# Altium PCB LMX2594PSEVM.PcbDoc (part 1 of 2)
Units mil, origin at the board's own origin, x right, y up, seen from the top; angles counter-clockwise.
Board outline 1260 x 3135 mil, 4 copper layers (Top Layer, GND, Power, Bottom Layer), stack 61.6 mil thick; 123 components, 80 nets, 426 pads, 190 vias.
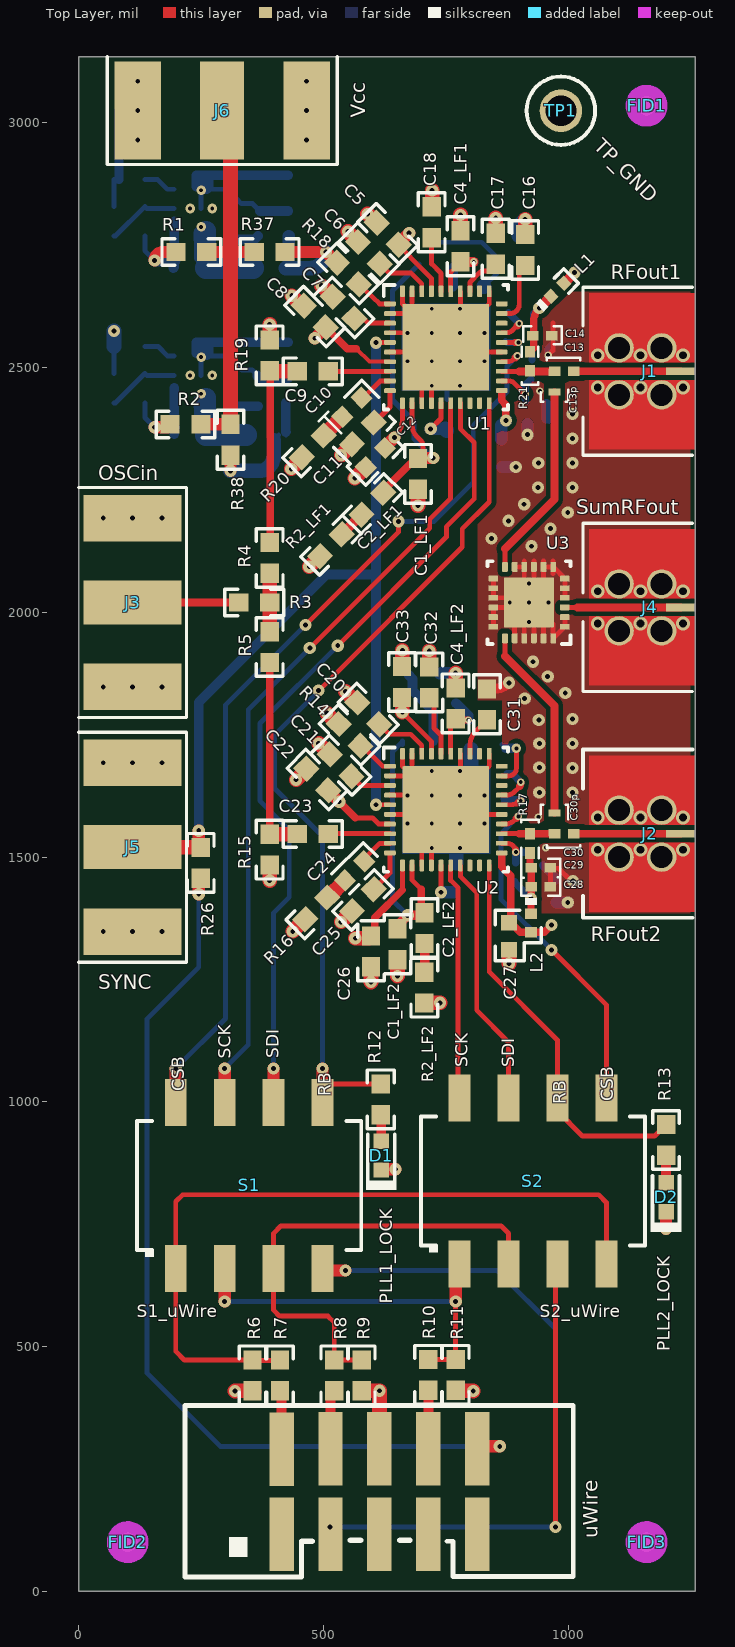
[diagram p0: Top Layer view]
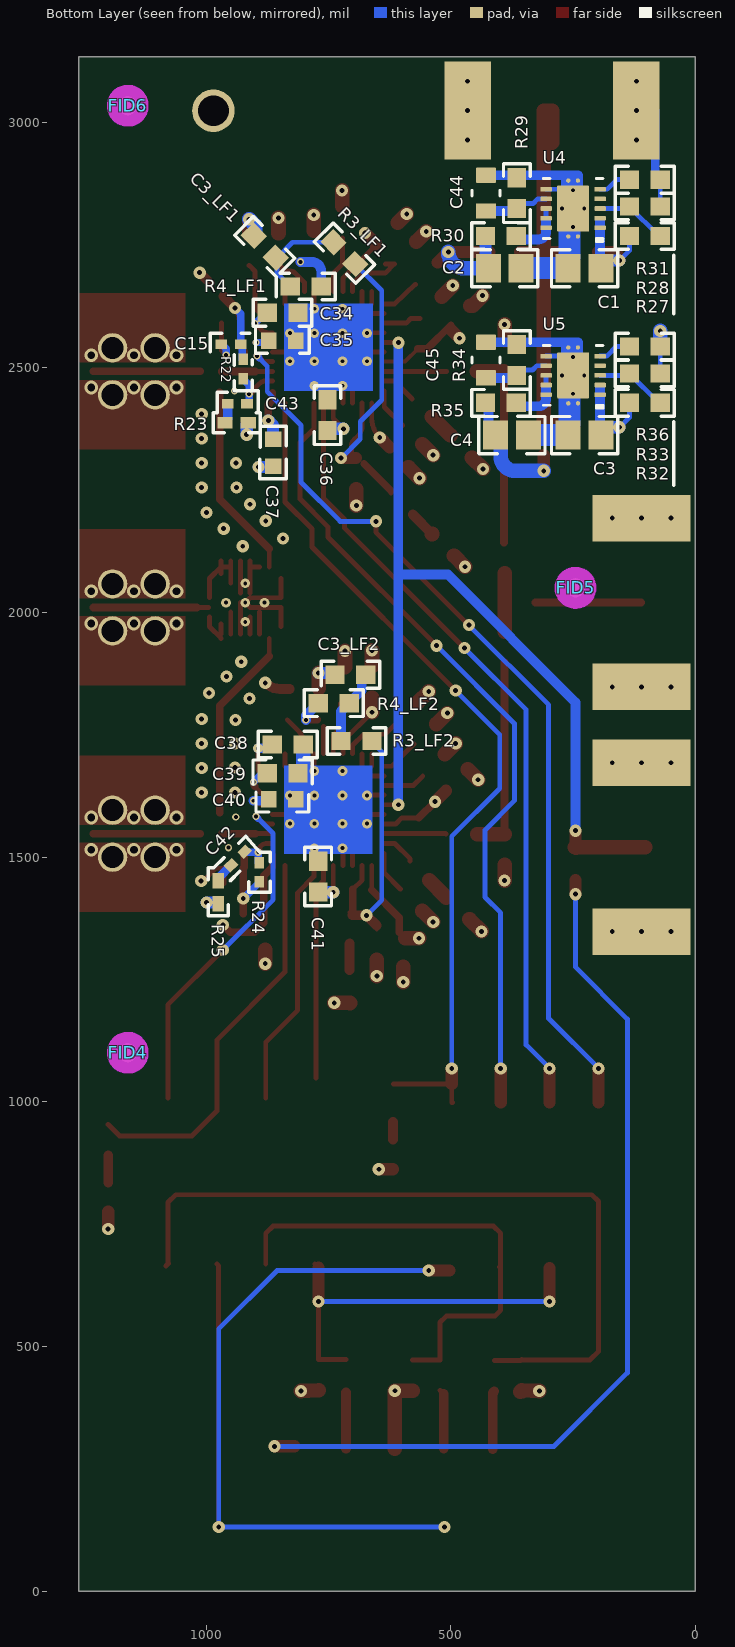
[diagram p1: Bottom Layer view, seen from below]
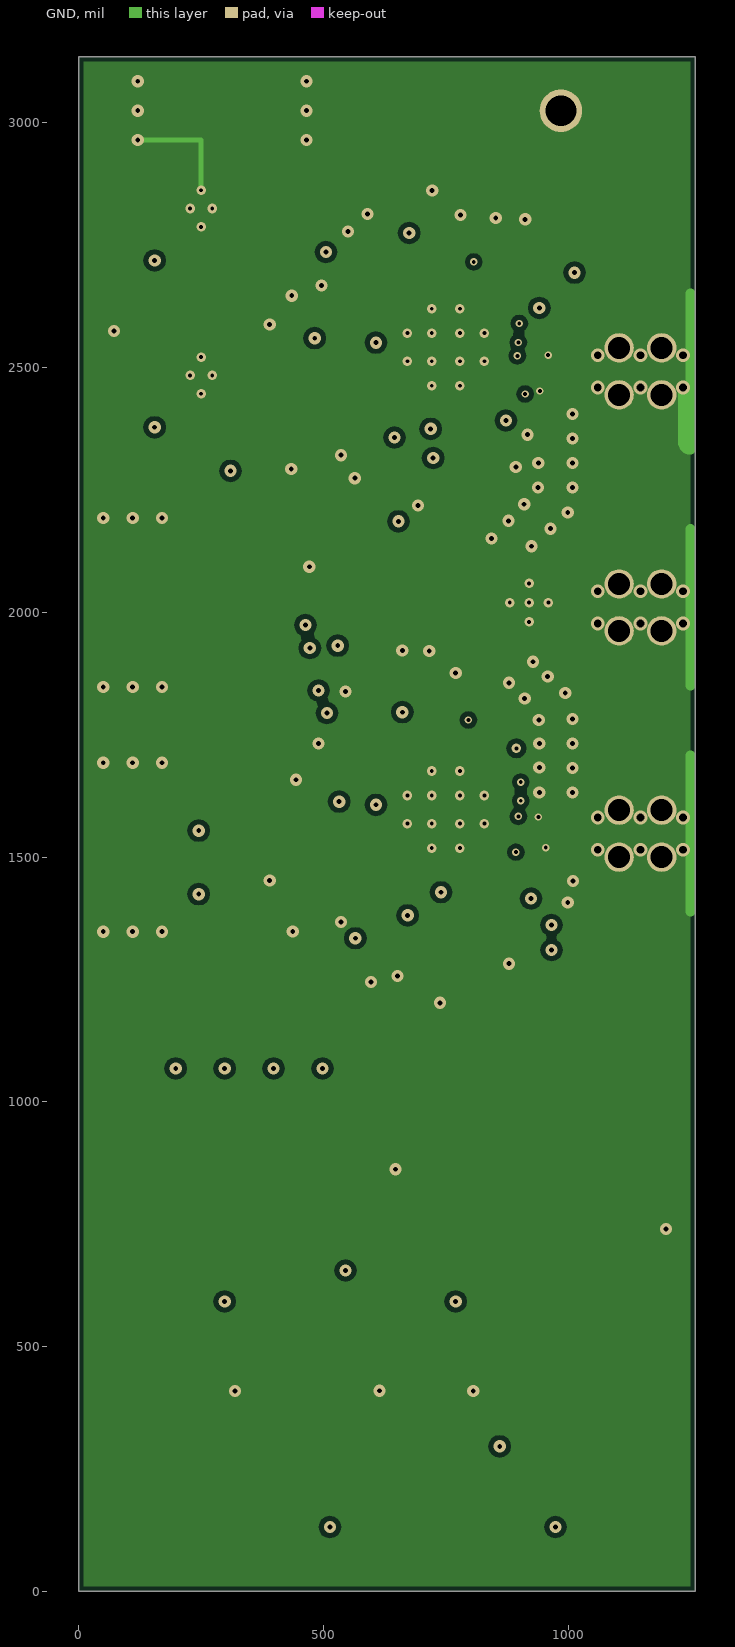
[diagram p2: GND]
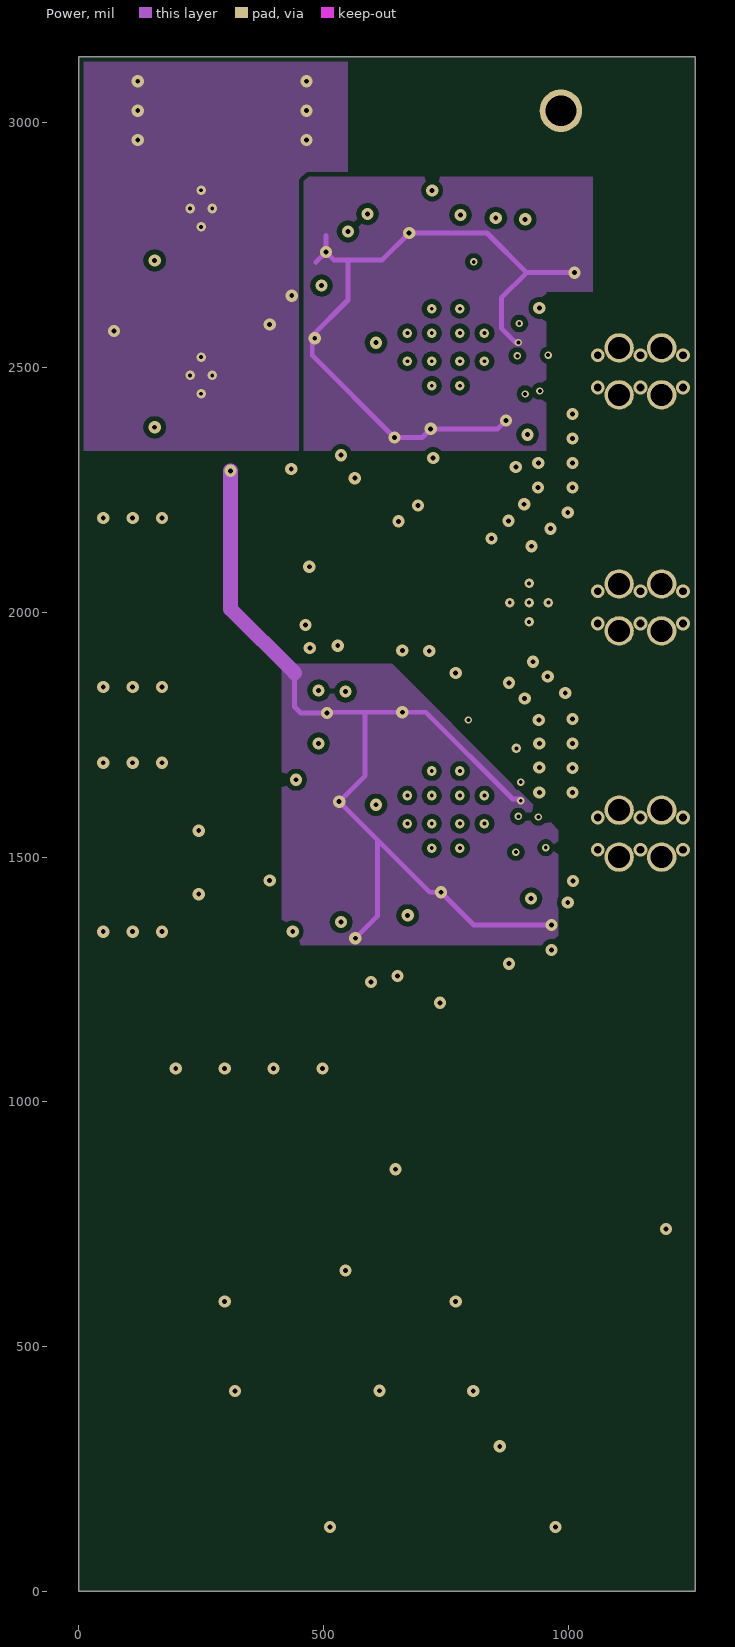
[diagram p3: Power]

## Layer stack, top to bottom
Top Solder: solder mask 0.4, Solder Resist, Dk 3.5
Top Layer: signal copper 1.4
Dielectric 1: prepreg 8, RO4350B, Dk 3.66
GND: signal copper 1.4
Dielectric 2: core 40, FR-4 High Tg, Dk 4.2
Power: signal copper 1.4
Dielectric 3: prepreg 8, FR-4 High Tg, Dk 4.2
Bottom Layer: signal copper 1.4
Bottom Solder: solder mask 0.4, Solder Resist, Dk 3.5

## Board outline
0,-0.14 0,3134.86 1260,3134.86 1260,-0.14

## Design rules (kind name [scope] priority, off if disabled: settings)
AcuteAngle [All] p1: minimum=4.50000000000000E+0001 checktracksonly=FALSE
AssemblyTestPointUsage [All] p1: valid=2
BoardOutlineClearance BoardOutlineClearance_MountingHoles [OnCopper and InComponentClass('Mounting Holes')] p1: gap=39.37 ignorepadtopadclearanceinfootprint=FALSE
BoardOutlineClearance BoardOutlineClearance_Poly [OnCopper and IsPoly] p2: gap=25 ignorepadtopadclearanceinfootprint=FALSE except(10: Poly-OutlineEdge)
BoardOutlineClearance [OnCopper and not InComponentClass('Logo')and not InComponentClass('FiducialMark') and not InRegion (1000, 500, 4000, 800) and not InPoly and not InComponent('J1') and not InComponent('J2') and not InComponent('J3') and not InComponent('J4') and not InComponent('J5') and not InComponent('J6') and not IsVia and not InNet('NetC13_2') and not InNet('NetC30_1') and not InNet('NetJ4_1') and not InNet('GND')] p3: gap=40 ignorepadtopadclearanceinfootprint=FALSE
Clearance Clearance_Keepouts [((IsTrack or IsArc) and not InPoly) and IsFree and IsKeepOut vs ((IsTrack or IsArc) and not InPoly) and IsFree and IsKeepOut] p1: gap=0 ignorepadtopadclearanceinfootprint=FALSE
Clearance Clearance_Poly [InPolygon] p2: gap=10 ignorepadtopadclearanceinfootprint=TRUE
Clearance Clearance_FiducialMark [IsKeepOut and InComponentClass('FiducialMark') vs IsPad and InComponentClass('FiducialMark')] p3: gap=0 ignorepadtopadclearanceinfootprint=FALSE
Clearance [All] p4: gap=7.87 ignorepadtopadclearanceinfootprint=TRUE
ComponentClearance ComponentClearance_MountingHoles_FiducialMarks [InComponentClass('Mounting Holes') vs InComponentClass('FiducialMark')] p1: gap=50 collisioncheckmode=3 verticalgap=10 showdistances=FALSE
ComponentClearance ComponentClearance_Shunt [InComponentClass('Header') vs InComponentClass('Shunt')] p2: gap=0 collisioncheckmode=3 verticalgap=0 showdistances=FALSE
ComponentClearance ComponentClearance_Logo [InComponentClass('Logo')] p3: gap=30 collisioncheckmode=3 verticalgap=10 showdistances=FALSE
ComponentClearance ComponentClearance_ScrewToNut [(HasFootprint('NY PMS 440 0025 PH')) vs (HasFootprint('Keystone_1902C'))] p4: gap=5 collisioncheckmode=3 verticalgap=10 showdistances=FALSE
ComponentClearance ComponentClearance_MountingHoles [InComponentClass('Mounting Holes')] p5: gap=100 collisioncheckmode=3 verticalgap=100000 showdistances=FALSE
ComponentClearance ComponentClearance_SmallPassives [not InComponent('C13') and not InComponent('C13p') and not InComponent('C30') and not InComponent('C30p') vs HasFootprint('0201*') or HasFootprint('0402*') or HasFootprint('0508') or HasFootprint('0603*') or HasFootprint('0612') or HasFootprint('0805*') or HasFootprint('0815*') or HasFootprint('0830*') or HasFootprint('1206*') or HasFootprint('1210*') or HasFootprint('1808*') or HasFootprint('1812*') or HasFootprint('1825*') or HasFootprint('2010*') or HasFootprint('2220*') or HasFootprint('2225*') or HasFootprint('2512*') or HasFootprint('2728*') or HasFootprint('3518*') or HasFootprint('IND_LQG*')] p6: gap=14.96 collisioncheckmode=3 verticalgap=10 showdistances=FALSE
ComponentClearance ComponentClearance_THtoSMT [IsThruComponent vs IsSMTComponent] p7: gap=30 collisioncheckmode=3 verticalgap=30 showdistances=FALSE
ComponentClearance ComponentClearance_THtoTH [IsThruComponent vs IsThruComponent] p8: gap=20 collisioncheckmode=3 verticalgap=30 showdistances=FALSE
ComponentClearance [not InComponent('C13') and not InComponent('C13p') and not InComponent('C30') and not InComponent('C30p')] p9: gap=20 collisioncheckmode=3 verticalgap=10 showdistances=FALSE
DiffPairsRouting [All] p1 off: maxlimit=100 minlimit=10 mostfreqgap=10 toplayer_minwidth=15 toplayer_maxwidth=15 toplayer_prefwidth=15 midlayer1_minwidth=15 midlayer1_maxwidth=15 midlayer1_prefwidth=15 midlayer2_minwidth=15 midlayer2_maxwidth=15 midlayer2_prefwidth=15 bottomlayer_minwidth=15 bottomlayer_maxwidth=15 bottomlayer_prefwidth=15 maxuncoupledlength=1000
FabricationTestPointUsage TestPointUsage [All] p1: valid=2 allowmultiple=FALSE
FabricationTestpoint Testpoint [All] p1: side=3 testpointundercomponent=TRUE minsize=40 maxsize=100 preferedsize=60 minholesize=0 maxholesize=40 preferedholesize=32 testpointgrid=1 allowsidetop=TRUE allowsidebottom=TRUE usegrid=TRUE gridtolerance=0.01
FanoutControl Fanout_LCC [IsLCC] p1 off: bgadir=Out bgaviamode=Centered fanoutstyle=Auto fanoutdirection=Alternating viagrid=1 // Fanout_LCC (Default Rule)
FanoutControl Fanout_BGA [IsBGA] p2: bgadir=Out bgaviamode=Centered fanoutstyle=Auto fanoutdirection=Alternating viagrid=1 // Fanout_BGA (Default Rule)
FanoutControl Fanout_Default [All] p4: bgadir=Out bgaviamode=Centered fanoutstyle=Auto fanoutdirection=Alternating viagrid=1 // Fanout_Default (Default Rule)
FanoutControl Fanout_Small [(CompPinCount < 5)] p5: bgadir=Out bgaviamode=Centered fanoutstyle=Auto fanoutdirection=OutThenIn viagrid=1 // Fanout_Small (Default Rule)
Height [All] p1 off: minheight=0 maxheight=1000 prefheight=500
HoleSize [All] p1 off: absolutevalues=TRUE maxlimit=251 minlimit=7.87 maxpercent=80.000 minpercent=20.000
MinimumAnnularRing MinimumAnnularRing_ThermalPadVias [IsVia and InAnyComponent] p1: minimumring=3.94
MinimumAnnularRing [All] p2: minimumring=3.5
MinimumSolderMaskSliver MinimumSolderMaskSliver_Logo [InComponentClass('Logo') vs InComponentClass('Logo')] p1: minsoldermaskwidth=3
MinimumSolderMaskSliver [All and not (InComponent('RFout1') or InComponent('RFout2')or InComponent('SumRFout')) and not InComponent('U3')] p2: minsoldermaskwidth=3.94
NetAntennae [All] p1: netantennaetolerance=1
PlaneConnect [All] p1: planeconnectstyle=Direct reliefexpansion=10 reliefentries=4 reliefconductorwidth=10 reliefairgap=10
PolygonConnect [All] p1: connectstyle=Direct reliefconductorwidth=15 reliefentries=4 polygonreliefangle="90 Angle" airgapwidth=10
RoutingVias [All] p1: holewidth=10 width=25 viastyle="Through Hole" minholewidth=2 minwidth=5 maxholewidth=16 maxwidth=30
RoutingVias ThermalPadVias [IsVia and InAnyComponent] p2: holewidth=7.87 width=19.68 viastyle="Through Hole" minholewidth=2 minwidth=5 maxholewidth=12.99 maxwidth=23.62
SMDToCorner [All] p1: distance=30000
SilkToSilkClearance SilkToSilkClearance_Pb-FreeLogo [(HasFootprint('Pb-Free_Overlay_Medium') or HasFootprint('Pb-Free_Overlay_Small')) vs (HasFootprint('Pb-Free_Overlay_Medium') or HasFootprint('Pb-Free_Overlay_Small'))] p1: silktosilkclearance=0
SilkToSilkClearance [All] p2: silktosilkclearance=3.94
SilkToSolderMaskClearance SilkscreenOverComponentPads [IsPad] p1: minsilkscreentomaskgap=3 clearancetoexposedcopper=TRUE
SolderMaskExpansion [All] p1: expansion=1.97
UnRoutedNet [All] p1: checkbadconnections=TRUE
Width [All] p1: maxlimit=200 minlimit=5 preferedwidth=5 checkconnectedcopper=TRUE
13 further rules are at their usual default settings.

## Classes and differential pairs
component class LMX2594PSEVM_SYNTH2: C1_LF2 C2_LF2 C3_LF2 C4_LF2 C20 C21 C22 C23 C24 C25 C26 C27 C28 C29 C30 C30p C31 C32 C33 C38 C39 C40 C41 C42 J2 L2 R2_LF2 R3_LF2 R4_LF2 R14 R15 R16 R17 R24 R25 U2
component class LMX2594PSEVM_HW: C1 C2 C3 C4 C44 C45 D1 D2 FID1 FID2 FID3 FID4 FID5 FID6 J3 J4 J5 J6 R1 R2 R3 R4 R5 R6 R7 R8 R9 R10 R11 R12 R13 R26 R27 R28 R29 R30 R31 R32 R33 R34 R35 R36 R37 R38 S1 S2 TP1 U3 U4 U5 uWire
component class FiducialMark: FID1 FID2 FID3 FID4 FID5 FID6
component class LMX2594PSEVM_SYNTH1: C1_LF1 C2_LF1 C3_LF1 C4_LF1 C5 C6 C7 C8 C9 C10 C11 C12 C13 C13p C14 C15 C16 C17 C18 C34 C35 C36 C37 C43 J1 L1 R2_LF1 R3_LF1 R4_LF1 R18 R19 R20 R21 R22 R23 U1

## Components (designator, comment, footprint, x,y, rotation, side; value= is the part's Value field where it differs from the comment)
C1 "EMK212BB7106KG-T" 0805 226.54,2703 r180 bottom value=10uF
C1_LF1 "06035A391JAT2A" 0603 693,2282.86 r270 top value=390pF
C1_LF2 "06035A391JAT2A" 0603 651.28,1321.69 r270 top value=390pF
C2 "EMK212BB7106KG-T" 0805 389.54,2703 r0 bottom value=10uF
C2_LF1 "885012206070" 0603 599.95,2221.81 r225 top value=0.068uF
C2_LF2 "885012206070" 0603 706.21,1354.86 r270 top value=0.068uF
C3 "EMK212BB7106KG-T" 0805 226.54,2362 r180 bottom value=10uF
C3_LF1 "GRM1885C1H301JA01D" 0603 880,2747 r45 bottom value=300pF
C3_LF2 "GRM1885C1H301JA01D" 0603 705.04,1872.36 r0 bottom value=300pF
C4 "EMK212BB7106KG-T" 0805 375,2362 r0 bottom value=10uF
C4_LF1 "Capacitor" 0603 780,2748 r90 top value=1800pF
C4_LF2 "Capacitor" 0603 770,1813.86 r90 top value=1800pF
C5 "Capacitor" 0603 631.12,2773.57 r135 top value=0.1uF
C6 "885012206052" 0603 592.83,2734.2 r135 top value=1uF
C7 "GRM188R61A106KAALD" 0603 540.81,2622.67 r135 top value=10uF
C8 "Capacitor" 0603 482.19,2604.36 r315 top value=0.1uF
C9 "Capacitor" 0603 478,2492.35 r0 top value=0.1uF
C10 "Capacitor" 0603L 558,2419 r45 top value=0.1uF
C11 "885012206052" 0603 580.51,2365.57 r45 top value=1uF
C12 "Capacitor" 0603L 606,2316 r45 top value=0.1uF
C13 "Capacitor" 0402_065L 992,2492.36 r0 top value=0.1uF
C13p "C0402C103J5RACTU" 0402S 972,2470 r270 top value=0.01uF
C14 "Capacitor" 0402_065L 947,2565 r180 top value=0.1uF
C15 "Capacitor" 0402_065L 949,2548 r180 bottom value=0.1uF
C16 "GRM188R61A106KAALD" 0603 912.05,2740.25 r90 top value=10uF
C17 "GRM188R61A106KAALD" 0603 852,2742.86 r90 top value=10uF
C18 "GRM188R61A106KAALD" 0603 721,2796.86 r90 top value=10uF
C20 "885012206052" 0603 591.49,1793.44 r135 top value=1uF
C21 "GRM188R61A106KAALD" 0603 535,1687.44 r315 top value=10uF
C22 "Capacitor" 0603 487.24,1658.37 r315 top value=0.1uF
C23 "Capacitor" 0603 478,1547 r0 top value=0.1uF
C24 "Capacitor" 0603L 563.61,1471.74 r45 top value=0.1uF
C25 "885012206052" 0603 580.41,1412.07 r45 top value=1uF
C26 "Capacitor" 0603 597,1307 r90 top value=0.1uF
C27 "Capacitor" 0603L 879,1338.25 r270 top value=0.1uF
C28 "Capacitor" 0402_065L 944,1439 r180 top value=0.1uF
C29 "Capacitor" 0402_065L 944,1478 r180 top value=0.1uF
C30 "Capacitor" 0402_065L 992,1547.65 r180 top value=0.1uF
C30p "C0402C103J5RACTU" 0402S 972,1570 r270 top value=0.01uF
C31 "GRM188R61A106KAALD" 0603 834,1812 r270 top value=10uF
C32 "GRM188R61A106KAALD" 0603 716,1856.86 r270 top value=10uF
C33 "Capacitor" 0603 660.19,1857.57 r90 top value=0.1uF
C34 "885012206052" 0603 843.71,2612 r0 bottom value=1uF
C35 "Capacitor" 0603L 844,2555 r180 bottom value=0.1uF
C36 "Capacitor" 0603 752,2402.86 r270 bottom value=0.1uF
C37 "Capacitor" 0603L 863,2326 r270 bottom value=0.1uF
C38 "GRM188R61A106KAALD" 0603 833,1730 r180 bottom value=10uF
C39 "885012206052" 0603 843.71,1671 r0 bottom value=1uF
C40 "Capacitor" 0603L 844,1617.72 r180 bottom value=0.1uF
C41 "Capacitor" 0603 771,1460 r270 bottom value=0.1uF
C42 "Capacitor" 0402_065L 935,1497 r135 bottom value=0.1uF
C43 "Capacitor" 0402_065L 936,2426 r180 bottom value=0.1uF
C44 "CGA4J1X7R1H475K125AC" FP-CGA4J1X7R1H475K125AC_0805-MFG 428,2856.42 r270 bottom value=4.7µF
C45 "CGA4J1X7R1H475K125AC" FP-CGA4J1X7R1H475K125AC_0805-MFG 428,2515.42 r270 bottom value=4.7µF
D1 "PLL1_LOCK" LED_LTST-C190 618,890 r270 top value=Green
D2 "PLL2_LOCK" LED_LTST-C190 1200,804.86 r270 top value=Green
FID1 "Fiducial" Fiducial10-20 1160,3035 r0 top
FID2 "Fiducial" Fiducial10-20 100,100 r0 top
FID3 "Fiducial" Fiducial10-20 1160,100 r0 top
FID4 "Fiducial" Fiducial10-20 1160,1100 r180 bottom
FID5 "Fiducial" Fiducial10-20 245,2050 r180 bottom
FID6 "Fiducial" Fiducial10-20 1160,3035 r180 bottom
J1 "RFout1" Johnson_142-0761-881 1147.5,2492.36 r270 top
J2 "RFout2" Johnson_142-0761-881 1147.5,1547.65 r270 top
J3 "OSCin" Emerson_142-0701-851 0,2020 r90 top
J4 "SumRFout" Johnson_142-0761-881 1147.5,2009.92 r270 top
J5 "SYNC" Emerson_142-0701-851 0,1520 r90 top
J6 "Vcc" Emerson_142-0701-851 293,3135 r0 top
L1 "Inductor_Iron" IND_LQG15H 978,2659 r45 top value=18nH
L2 "Inductor_Iron" IND_LQG15H 924,1365 r270 top value=18nH
R1 "Resistor" 0603 230,2736 r180 top value=0
R2 "Resistor" 0603 218,2384 r180 top value=0
R2_LF1 "Resistor" 0603 515,2137 r225 top value=68
R2_LF2 "Resistor" 0603 706,1233 r270 top value=68
R3 "Resistor" 0603 358.5,2020 r0 top value=18
R3_LF1 "Resistor" 0603 717.31,2733.8 r45 bottom value=18
R3_LF2 "Resistor" 0603 692.59,1736.95 r0 bottom value=18
R4 "Resistor" 0603 390,2111 r90 top value=18
R4_LF1 "Resistor" 0603 796.21,2665.82 r180 bottom value=0
R4_LF2 "Resistor" 0603 739.17,1814.27 r0 bottom value=0
R5 "Resistor" 0603 390,1929 r90 top value=18
R6 "Resistor" 0603 355,440.86 r90 top value=12k
R7 "CRCW060318R0JNEA" 0603 411,440.86 r90 top value=18
R8 "CRCW060318R0JNEA" 0603 522,440.86 r270 top value=18
R9 "Resistor" 0603 578,440.86 r90 top value=12k
R10 "CRCW060318R0JNEA" 0603 714,441.86 r90 top value=18
R11 "Resistor" 0603 770,441.86 r90 top value=12k
R12 "Resistor" 0603 617,1004.86 r90 top value=330
R13 "Resistor" 0603 1200,921.86 r90 top value=330
R14 "Resistor" 0603 553.29,1749.39 r315 top value=12k
R15 "Resistor" 0603 390,1515 r90 top value=51
R16 "Resistor" 0603 485,1395 r45 top value=51
R17 "Resistor" 0402L 922,1527.86 r90 top value=50
R18 "Resistor" 0603 549.81,2692.29 r315 top value=12k
R19 "Resistor" 0603 390,2525 r270 top value=51
R20 "Resistor" 0603 478,2339 r45 top value=51
R21 "Resistor" 0402L 922,2512.86 r270 top value=50
R22 "Resistor" 0402L 924,2497 r90 bottom value=50
R23 "Resistor" 0402 937.61,2387 r180 bottom value=50
R24 "Resistor" 0402L 891,1468.92 r270 bottom value=50
R25 "Resistor" 0402 975,1428 r270 bottom value=50
R26 "Resistor" 0603 249,1488 r270 top value=0
R27 "Resistor" 0603 103.5,2769 r0 bottom value=12k
R28 "Resistor" 0603 103.5,2829 r0 bottom value=12k
R29 "CRCW060322K1FKEA" 0603 365,2856.5 r270 bottom value=22.1k
R30 "Resistor" 0603 397.5,2769 r0 bottom value=0
R31 "Resistor" 0603 103.5,2884 r0 bottom value=12k
R32 "Resistor" 0603 103.5,2428 r0 bottom value=12k
R33 "Resistor" 0603 103.5,2488 r0 bottom value=12k
R34 "CRCW060322K1FKEA" 0603 365,2515.5 r270 bottom value=22.1k
R35 "Resistor" 0603 397.5,2428 r0 bottom value=0
R36 "Resistor" 0603 103.5,2543 r0 bottom value=12k
R37 "Resistor" 0603 390,2736 r0 top value=0
R38 "Resistor" 0603 310,2352.5 r270 top value=0
S1 "S1_uWire" SW_219-4MST 348,828.86 r90 top
S2 "S2_uWire" SW_219-4MST 928,837.86 r90 top
TP1 "TP_GND" Keystone5007 985,3024.86 r90 top
U1 "LMX2594RHAR" RHA0040H 750,2541.57 r0 top
U2 "LMX2594RHAR" RHA0040H 750,1596.86 r0 top
U3 "EP2C+" DG1847 920,2019.77 r180 top
U4 "TPS7A9401DSC" DSC0010J-MFG 250,2825 r0 bottom
U5 "TPS7A9401DSC" DSC0010J-MFG 250,2484 r0 bottom
uWire "Header_5x2" FCI_52601-S10-8LF 614.27,203.51 r90 top

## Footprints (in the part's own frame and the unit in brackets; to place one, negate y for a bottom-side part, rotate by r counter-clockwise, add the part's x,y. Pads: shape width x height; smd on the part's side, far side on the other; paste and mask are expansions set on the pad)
0402 [mm] "0402 from SM-752 data"
  rect 0.8x0.6 smd: 1(-0.6,0) 2(0.6,0)
  silkscreen extent -1.22,-1.27 1.23,1.6, body extent -0.55,-0.3 0.55,0.3, height 0.6
0402_065L [mm] "0402"
  rect 0.6x0.5 smd: 1(-0.5,0) 2(0.5,0)
  body extent -0.55,-0.3 0.55,0.3, height 0.65
0402L [mm] "0402 from SM-752 data"
  rect 0.6x0.5 smd: 1(-0.5,0) 2(0.5,0)
  body extent -0.55,-0.3 0.55,0.3, height 0.6
0402S [mil] "Based on C0402S footprint from PADS legacy"
  rect 15x24 smd: 1(-20,0) 2(20,0)
  body extent -22,-12 22,12, height 24
0603 [mm] "0603 from SM-752 data"
  rect 1x0.95 smd: 1(-0.8,0) 2(0.8,0)
  silkscreen extent -1.52,-0.69 1.52,0.69, body extent -0.87,-0.47 0.87,0.47, height 1
0603L [mm] "0603 from SM-752 data"
  rect 0.8x0.85 smd: 1(-0.7,0) 2(0.7,0)
  body extent -0.87,-0.47 0.87,0.47, height 1
0805 [mm] "0805 from SM-752 data"
  rect 1.3x1.5 smd: 1(-0.85,0) 2(0.85,0)
  silkscreen extent -1.72,-0.97 1.72,0.97, body extent -1.1,-0.72 1.1,0.72, height 1.45
DG1847 [mm] "QFN, 24-Leads, Body 4x4mm, Pitch 0.5mm"
  rrect33% 0.51x0.3 smd: 1(-1.855,1.25) 2(-1.855,0.75) 3(-1.855,0.25) 4(-1.855,-0.25) 5(-1.855,-0.75) 6(-1.855,-1.25) 13(1.855,-1.25) 14(1.855,-0.75) 15(1.855,-0.25) 16(1.855,0.25) 17(1.855,0.75) 18(1.855,1.25)
  rrect33% 0.3x0.51 smd: 7(-1.25,-1.855) 8(-0.75,-1.855) 9(-0.25,-1.855) 10(0.25,-1.855) 11(0.75,-1.855) 12(1.25,-1.855) 19(1.25,1.855) 20(0.75,1.855) 21(0.25,1.855) 22(-0.25,1.855) 23(-0.75,1.855) 24(-1.25,1.855)
  rrect4% 2.59x2.59 smd paste-2: 25(0,0)
  rrect9% 1.106x1.106 on Top Paste: ""(-0.653,0.653) ""(-0.653,-0.653) ""(0.653,0.653) ""(0.653,-0.653)
  silkscreen extent -2.15,-2.15 2.15,2.15, body extent -2,-2 2,2, height 1
DSC0010J-MFG [mm]
  rrect42% 0.6x0.24 smd paste+0 mask+0: 1(-1.4,1) 2(-1.4,0.5) 3(-1.4,0) 4(-1.4,-0.5) 5(-1.4,-1) 6(1.4,-1) 7(1.4,-0.5) 8(1.4,0) 9(1.4,0.5) 10(1.4,1)
  round 0.225 smd paste-1000 mask+0: 11(-0.25,-1.45) 11(-0.25,1.448) 11(0.25,-1.448) 11(0.25,1.45)
  rrect6% 1.65x2.4 smd paste-1000 mask+0: 11(0,0)
  Top Layer region: -0.375,1.2 -0.375,1.65 -0.371,1.669 -0.36,1.685 -0.344,1.696 -0.325,1.7 -0.325,1.7 -0.175,1.7 -0.156,1.696 -0.14,1.685 -0.129,1.669 -0.125,1.65 -0.125,1.65 -0.125,1.2
  Top Layer region: 0.125,1.2 0.125,1.65 0.129,1.669 0.14,1.685 0.156,1.696 0.175,1.7 0.175,1.7 0.325,1.7 0.344,1.696 0.36,1.685 0.371,1.669 0.375,1.65 0.375,1.65 0.375,1.2
  Top Layer region: -0.125,-1.2 -0.125,-1.65 -0.132,-1.675 -0.15,-1.693 -0.175,-1.7 -0.175,-1.7 -0.325,-1.7 -0.344,-1.696 -0.36,-1.685 -0.371,-1.669 -0.375,-1.65 -0.375,-1.65 -0.375,-1.2
  Top Layer region: 0.375,-1.2 0.375,-1.65 0.368,-1.675 0.35,-1.693 0.325,-1.7 0.325,-1.7 0.175,-1.7 0.156,-1.696 0.14,-1.685 0.129,-1.669 0.125,-1.65 0.125,-1.65 0.125,-1.2
  silkscreen extent -1.55,-1.55 1.55,1.55, body extent -1.5,-1.5 1.5,1.5, height 0.8
Emerson_142-0701-851 [mil] "Cinch Connectivity"
  rect 90x200 smd: 1(0,-110)
  rect 95x200 smd: 2(-172.5,-110) 3(172.5,-110)
  rect 95x200 smd far side: 4(172.5,-110) 5(-172.5,-110)
  silkscreen extent -235,-220 235,0, body extent -190,-195 190,387, height 155
FCI_52601-S10-8LF [mil] "FCI Electronics"
  rect 150x50 smd: 1(-87.5,200) 2(86.5,200) 3(-87.5,100) 4(87.5,100) 5(-87.5,0) 6(87.5,0) 7(-87.5,-100) 8(87.5,-100) 9(-87.5,-200) 10(87.5,-200)
  silkscreen extent -175,-396 176,397, body extent -172,-395 173,395, height 496
Fiducial10-20 [mm]
  round 1 smd mask+0.5: 1(0,0)
  Top Layer keep-out circle w1.178: c0,0 r0.5
FP-CGA4J1X7R1H475K125AC_0805-MFG [mm]
  rrect13% 0.8x1.05 smd paste+0 mask+0: 1(-0.925,0) 2(0.925,0)
  silkscreen extent -0.15,-0.72 0.15,0.72, body extent -1,-0.63 1,0.63, height 1.45
IND_LQG15H [mm] "MuRata"
  rect 0.55x0.6 smd: 1(-0.475,0) 2(0.475,0)
  silkscreen extent -1.3,-0.3 -0.95,0.3, body extent -0.52,-0.27 0.52,0.27, height 0.55
Johnson_142-0761-881 [mil] "Connector, TH, End launch SMA"
  rect 16x60 smd: 1(0,82.5)
  round 60 hole 45 mask+0: 2(-48,43.5) 3(-48,-43.5) 4(48,-43.5) 5(48,43.5)
  Top Layer region: 18,-105.48 160,-105.48 160,112.52 18,112.52
  Top Layer region: -18,112.52 -160,112.52 -160,-105.48 -18,-105.48
  silkscreen extent -172,-117 172,106, body extent -124,-67 123,497, height 128
Keystone5007 [mil] "Keystone Compact loops"
  round 87 hole 63: 1(0,0)
  silkscreen extent -70,-70 70,70, body extent -63,-63 62,63, height 225
LED_LTST-C190 [mm] "Lite-On"
  rect 0.8x0.8 smd: 1(-0.75,0) 2(0.75,0)
  silkscreen extent -1.1,-0.8 1.8,0.8, body extent -0.85,-0.45 0.85,0.45, height 0.9
RHA0040H [mm] "QFN, 40-Leads, Body 6x6mm, Pitch 0.5mm, Thermal Pad 4.15 x 4.15mm, TI Recommended"
  rrect40% 0.6x0.25 smd: 1(-2.9,2.25) 2(-2.9,1.75) 3(-2.9,1.25) 4(-2.9,0.75) 5(-2.9,0.25) 6(-2.9,-0.25) 7(-2.9,-0.75) 8(-2.9,-1.25) 9(-2.9,-1.75) 10(-2.9,-2.25) 21(2.9,-2.25) 22(2.9,-1.75) 23(2.9,-1.25) 24(2.9,-0.75) 25(2.9,-0.25) 26(2.9,0.25) 27(2.9,0.75) 28(2.9,1.25) 29(2.9,1.75) 30(2.9,2.25)
  rrect40% 0.25x0.6 smd: 11(-2.25,-2.9) 12(-1.75,-2.9) 13(-1.25,-2.9) 14(-0.75,-2.9) 15(-0.25,-2.9) 16(0.25,-2.9) 17(0.75,-2.9) 18(1.25,-2.9) 19(1.75,-2.9) 20(2.25,-2.9) 31(2.25,2.9) 32(1.75,2.9) 33(1.25,2.9) 34(0.75,2.9) 35(0.25,2.9) 36(-0.25,2.9) 37(-0.75,2.9) 38(-1.25,2.9) 39(-1.75,2.9) 40(-2.25,2.9)
  rrect8% 1.26x1.26 on Top Paste: 41(-1.46,-1.46) 41(-1.46,0) 41(-1.46,1.46) 41(0,-1.46) 41(0,0) 41(0,1.46) 41(1.46,-1.46) 41(1.46,0) 41(1.46,1.46)
  rrect2% 4.5x4.5 smd paste-2.5: 41(0,0)
  silkscreen extent -3.22,-3.22 3.22,3.23, body extent -3,-3 3,3, height 1
SW_219-4MST [mm] "SMT, 8-Leads, Body 11.63x6.7mm, Pitch 2.54mm"
  rect 2.44x1.13 smd: 1(-4.3,3.81) 2(-4.3,1.27) 3(-4.3,-1.27) 4(-4.3,-3.81) 5(4.3,-3.81) 6(4.3,-1.27) 7(4.3,1.27) 8(4.3,3.81)
  silkscreen extent -3.7,-5.82 3.35,5.82, body extent -4.95,-5.82 4.95,5.82, height 4.32

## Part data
C1 C2 C3 C4: library part CMP-0085283-1, "CAP, CERM, 10 µF, 16 V,+/- 10%, X7R, 0805", Cap_Case=0805, Manufacturer="Taiyo Yuden", TempCo=X7R, Tolerance_%=10%, Value2=16V, ValueDisplayed=10µF
C1_LF1 C1_LF2: library part CMP-0006786-4, "CAP, CERM, 390 pF, 50 V, +/- 5%, C0G/NP0, 0603", Cap_Case=0603, Manufacturer=AVX, Supplier Part Number 1=478-1182-1-ND, TempCo=C0G/NP0, Tolerance_%=5%, Value1="0.067 ohm", Value2=50V, ValueDisplayed=390pF
C2_LF1 C2_LF2: library part CMP-0750069-1, "CAP, CERM, 0.068 µF, 25 V,+/- 10%, X7R, 0603", Cap_Case=0603, Manufacturer="Wurth Elektronik", TempCo=X7R, Tolerance_%=10%, Value2=25V, ValueDisplayed=0.068µF
C3_LF1 C3_LF2: library part CMP-0007206-4, "CAP, CERM, 300 pF, 50 V, +/- 5%, C0G/NP0, 0603", Cap_Case=0603, Manufacturer=MuRata, Supplier Part Number 1=490-1438-1-ND, TempCo=C0G/NP0, Tolerance_%=5%, Value1=Unknown, Value2=50V, ValueDisplayed=300pF
C4_LF1 C4_LF2: library part CMP-0007192-4, "CAP, CERM, 1800 pF, 50 V, +/- 5%, C0G/NP0, 0603", Cap_Case=0603, Manufacturer=MuRata, PartNumber=GRM1885C1H182JA01D, Supplier Part Number 1=490-1457-1-ND, TempCo=C0G/NP0, Tolerance_%=5%, Value1=Unknown, Value2=50V, ValueDisplayed=1.8nF
C5 C8 C9 C10 C12 C22 C23 C24 C26 C27 C33 C35 C36 C37 C40 C41: library part CMP-0006808-4, "CAP, CERM, 0.1 uF, 16 V, +/- 5%, X7R, 0603", Cap_Case=0603, Manufacturer=AVX, PartNumber=0603YC104JAT2A, Supplier Part Number 1=478-3726-1-ND, TempCo=X7R, Tolerance_%=5%, Value1="0.039 ohm", Value2=16V, ValueDisplayed=0.1µF
C6 C11 C20 C25 C34 C39: library part CMP-0006831-4, "CAP, CERM, 1 uF, 16 V, +/- 10%, X7R, 0603", Cap_Case=0603, Manufacturer="Wurth Elektronik", Supplier Part Number 1=710-885012206052, TempCo=X7R, Tolerance_%=10%, Value1=Unknown, Value2=16V, ValueDisplayed=1uF
C7 C16 C17 C18 C21 C31 C32 C38: library part CMP-0086193-1, "CAP, CERM, 10 µF, 10 V,+/- 10%, X5R, 0603", Cap_Case=0603, Manufacturer=MuRata, TempCo=X5R, Tolerance_%=10%, Value2=10V, ValueDisplayed=10µF
C13 C14 C15 C28 C29 C30 C42 C43: library part CMP-0006210-2, "CAP, CERM, 0.1 uF, 16 V, +/- 10%, X7R, 0402", Cap_Case=0402, Manufacturer="AT Ceramics", PartNumber=530L104KT16T, Supplier Part Number 1=1284-1591-1-ND, TempCo=X7R, Tolerance_%=10%, Value1=Unknown, Value2=16V, ValueDisplayed=100nF
C13p C30p: library part CMP-0006236-2, "CAP, CERM, 0.01 uF, 50 V, +/- 5%, X7R, 0402", Cap_Case=0402, Manufacturer=Kemet, Supplier Part Number 1=399-7758-1-ND, TempCo=X7R, Tolerance_%=5%, Value1=Unknown, Value2=50V, ValueDisplayed=10nF
C44 C45: library part CMP-0090082-1, "Cap Ceramic 4.7uF 50V X7R 10% Pad SMD 0805 +125°C Automotive T/R", Manufacturer="TDK Corporation", Operating Temperature Range="-55°C to +125°C", TempCo=15%, Temperature Characteristic=X7R, Tolerance_%=0.1%, ValueDisplayed=4.7uF
D1 D2: library part CMP-0002827-3, "LED, Green, SMD", Color=green, Manufacturer=Lite-On, PartNumber=LTST-C190GKT, Power_TotalModule=100mW, Value1=0.1W, Value2=2.1V
FID1 FID2 FID3 FID4 FID5 FID6: library part CMP-0077181-1, "Fiducial mark.  There is nothing to buy or mount.", Manufacturer=N/A
J1 J2 J4: library part CMP-0055835-1, "Connector, End launch SMA 50 ohm, TH", Manufacturer="Cinch Connectivity", PartNumber=142-0761-881, Supplier Part Number 1=J801-ND
J3 J5 J6: library part CMP-0055822-3, "Connector, End launch SMA, 50 ohm, SMT", Manufacturer="Cinch Connectivity", PartNumber=142-0701-851, Supplier Part Number 1=J658-ND
L1 L2: library part CMP-0058614-1, "Inductor, Multilayer, Air Core, 18 nH, 0.3 A, 0.36 ohm, SMD", Manufacturer=MuRata, PartNumber=LQG15HS18NJ02D, Supplier Part Number 1=490-2626-1-ND, Value1="0.36 ohm", Value2=0.3A, ValueDisplayed=18nH
R1 R2 R4_LF1 R4_LF2 R26 R30 R35 R37 R38: library part CMP-0025697-4, "RES, 0, 5%, 0.1 W, AEC-Q200 Grade 0, 0603", Manufacturer=Vishay-Dale, PartNumber=CRCW06030000Z0EA, Power_W=100mW, Supplier Part Number 1=541-0.0GCT-ND, TempCo="200 ppm/C", Tolerance_%=5%, Value2=0.1W, Value_Code=0000, ValueDisplayed=0
R2_LF1 R2_LF2: library part CMP-0025843-4, "RES, 68, 5%, 0.1 W, AEC-Q200 Grade 0, 0603", Manufacturer=Vishay-Dale, PartNumber=CRCW060368R0JNEA, Power_W=100mW, Supplier Part Number 1=541-68GCT-ND, TempCo="200 ppm/C", Tolerance_%=5%, Value2=0.1W, Value_Code=68R0, ValueDisplayed=68
R3 R3_LF1 R3_LF2 R4 R5: library part CMP-0025728-4, "RES, 18, 5%, 0.1 W, AEC-Q200 Grade 0, 0603", Manufacturer=Vishay-Dale, PartNumber=CRCW060318R0JNEA, Power_W=100mW, Supplier Part Number 1=541-18GCT-ND, TempCo="200 ppm/C", Tolerance_%=5%, Value2=0.1W, Value_Code=18R0, ValueDisplayed=18
R6 R9 R11 R14 R18 R27 R28 R31 R32 R33 R36: library part CMP-0025711-4, "RES, 12 k, 5%, 0.1 W, AEC-Q200 Grade 0, 0603", Manufacturer=Vishay-Dale, PartNumber=CRCW060312K0JNEA, Power_W=100mW, Supplier Part Number 1=541-12KGCT-ND, TempCo="200 ppm/C", Tolerance_%=5%, Value2=0.1W, Value_Code=12k0, ValueDisplayed=12k
R7 R8 R10: library part CMP-0025728-4, "RES, 18, 5%, 0.1 W, AEC-Q200 Grade 0, 0603", Manufacturer=Vishay-Dale, Power_W=100mW, Supplier Part Number 1=541-18GCT-ND, TempCo="200 ppm/C", Tolerance_%=5%, Value2=0.1W, Value_Code=18R0, ValueDisplayed=18
R12 R13: library part CMP-0025912-5, "RES, 330, 5%, 0.1 W, 0603", Manufacturer=Yageo, PartNumber=RC0603JR-07330RL, Power_W=100mW, Supplier Part Number 1=311-330GRCT-ND, TempCo="100 ppm/C", Tolerance_%=5%, Value2=0.1W, Value_Code=330R, ValueDisplayed=330
R15 R16 R19 R20: library part CMP-0025825-4, "RES, 51, 5%, 0.1 W, AEC-Q200 Grade 0, 0603", Manufacturer=Vishay-Dale, PartNumber=CRCW060351R0JNEA, Power_W=100mW, Supplier Part Number 1=541-51GCT-ND, TempCo="200 ppm/C", Tolerance_%=5%, Value2=0.1W, Value_Code=51R0, ValueDisplayed=51
R17 R21 R22 R23 R24 R25: library part CMP-0026791-1, "RES, 50, 0.1%, 0.05 W, 0402", Manufacturer=Vishay-Dale, PartNumber=FC0402E50R0BST1, Power_W=50mW, Supplier Part Number 1=FC0402-50BWCT-ND, TempCo="25 ppm/C", Tolerance_%=0.1%, Value2=0.05W, Value_Code=50R0, ValueDisplayed=50
R29 R34: library part CMP-0022220-4, "RES, 22.1 k, 1%, 0.1 W, AEC-Q200 Grade 0, 0603", Manufacturer=Vishay-Dale, Power_W=100mW, Supplier Part Number 1=541-22.1KHCT-ND, TempCo="100 ppm/C", Tolerance_%=1%, Value2=0.1W, Value_Code=22k1, ValueDisplayed=22.1k
S1 S2: library part CMP-0002291-1, "Switch, SPST, Slide, Off-On, 4 Pos, 0.1A, 20V, SMD", CurrentRating_mA=100A, Manufacturer="CTS Electrocomponents", PartNumber=219-4MST, Supplier Part Number 1=CT2194MST-ND
TP1: library part CMP-0055144-2, "Test Point, Compact, White, TH", Color=White, Manufacturer="Keystone Electronics", PartNumber=5007, Supplier Part Number 1=36-5007-ND
U1 U2: library part CMP-0013786-6, "15 GHz Wideband PLLatinum(TM)RF Synthesizer with Phase Synchronization and JESD204B support, RHA0040H (VQFN-40)", Alternate Manufacturer="Texas Instruments", Alternate PartNumber=LMX2594RHAT
U3: library part CMP-0065468-1, "Power Splitter/Combiner, 2 Way-0°, 50Ohm, 1800 to 12500 MHz", Manufacturer=Minicircuits
U4 U5: library part CMP-0091022-1, "1-A, Ultra-Low Noise, Ultra-High PSRR, RF Voltage Regulator", Dropout Voltage=210mV, Manufacturer="Texas Instruments", Max Supply Voltage=5.5V, Min Supply Voltage=1.7V, Nominal Supply Current=15-47mA, Operating Temperature Range="-40°C to +150°C", Output Voltage=0.4-5.3V
uWire: library part CMP-0055434-2, "Header (shrouded), 100mil, 5x2, Gold, SMT", Manufacturer=FCI, PartNumber=52601-S10-8LF, Supplier Part Number 1=609-3593-ND

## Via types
v1: diameter 25, hole 10, Top Layer to Bottom Layer, tented both sides, 120 vias
v2: diameter 19.68, hole 7.87, Top Layer to Bottom Layer, tented bottom, 29 vias
v3: diameter 28, hole 16, Top Layer to Bottom Layer, tented both sides, 18 vias
v4: diameter 15, hole 8, Top Layer to Bottom Layer, tented both sides, 14 vias
v5: diameter 19.68, hole 7.87, Top Layer to Bottom Layer, tented top, 8 vias
v6: diameter 20, hole 8, Top Layer to Bottom Layer, tented both sides, 1 vias

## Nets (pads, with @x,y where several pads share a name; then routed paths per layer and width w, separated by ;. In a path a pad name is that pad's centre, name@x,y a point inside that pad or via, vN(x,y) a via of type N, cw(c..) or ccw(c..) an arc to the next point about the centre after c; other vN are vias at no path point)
CSB: R6.2 R7.2 S1.1 S2.4 | length 1552.1
  Top Layer w10: R6.2@355,472.35 215.65,472.35 198,490 S1.1@198,659.57 198,796 212,810 1062,810 1078,794 S2.4@1078,668.57 ; R6.2@355,473.35 357,471.35 R7.2@411,471.35 ; S2.4@1077,669.57 S2.4@1078,668.57 ; S2.4@1082,664.57 S2.4@1078,668.57
CSB_U1: S1.8 U1.24 | length 1897.2
  Top Layer w10: v1(463,1973.86) 653,2163.86 v1(653,2185.86) ; U1.24@864.17,2512.04 875.61,2512.04 ccw(c875.61,2532.39) 890,2518
  Top Layer w15: v4@891.76,2519.76 v4(896,2524)
  Top Layer w25: S1.8@198,998.15 v1(198,1068)
  Bottom Layer w10: v1(198,1068) 300,1170 300,1810.86 v1(463,1973.86) ; v1(653,2185.86) 726,2185.86 806,2265.86 806,2382 875,2451 875,2503 v4(896,2524)
  Bottom Layer w15: v4@891.76,2519.76 v4(896,2524)
CSB_U2: S2.5 U2.24 | length 730.6
  Top Layer w10: U2.24@864.17,1567.33 871.49,1567.33 ccw(c871.49,1593.51) 890,1575 v4(898,1583) ; v1(966,1310) 1078,1198 S2.5@1078,1007.15
  Top Layer w15: v4@893.76,1578.76 v4(898,1583)
  Bottom Layer w10: v4(898,1583) 863,1548 863,1413 v1(966,1310)
  Bottom Layer w15: v4@893.76,1578.76 v4(898,1583)
GND: C1.1 C1_LF1.2 C1_LF2.2 C2.1 C3.1 C3_LF1.2 C3_LF2.2 C4.1 C4_LF1.2 C4_LF2.2 C5.2 C6.2 C7.2 C8.1 C11.1 C12.1 C14.1 C15.1 C16.2 C17.2 C18.2 C20.2 C21.1 C22.1 C25.1 C26.1 C27.2 C28.1 C29.1 C31.1 C32.1 C33.2 C34.1 C35.2 C36.1 C37.2 C38.2 C39.1 C40.2 C41.1 C44.1 C45.1 D1.2 D2.2 J1.2 J1.3 J1.4 J1.5 J2.2 J2.3 J2.4 J2.5 J3.2 J3.3 J3.4 J3.5 J4.2 J4.3 J4.4 J4.5 J5.2 J5.3 J5.4 J5.5 J6.2 J6.3 J6.4 J6.5 R2_LF1.2 R2_LF2.2 R6.1 R9.1 R11.1 R15.1 R16.1 R19.1 R20.1 R23.2 R25.2 R28.1 R29.1 R31.1 R33.1 R34.1 R36.1 TP1.1 U1.2 U1.4 U1.6 U1.13 U1.14 U1.25 U1.31 U1.34 U1.39 U1.40 U1.41@750,2541.57 U2.2 U2.4 U2.6 U2.13 U2.14 U2.25 U2.31 U2.34 U2.39 U2.40 U2.41@750,1596.86 U3.1 U3.2 U3.4 U3.5 U3.6 U3.7 U3.8 U3.9 U3.10 U3.11 U3.13 U3.14 U3.15 U3.16 U3.17 U3.18 U3.20 U3.21 U3.22 U3.23 U3.24 U3.25 U4.6 U4.11 U5.6 U5.11 uWire.6 | length 7349.1
  Top Layer w5: R16.1@461.8,1372.73 R16.1@462.73,1372.73
  Top Layer w8: U2.41@681.1,1665.76 720.47,1626.39 U2.41@750,1596.86
  Top Layer w10: U2.6@635.83,1587.02 U2.41@740.16,1587.02 ; U2.4@635.83,1626.39 U2.41@720.47,1626.39 ; U2.2@635.83,1665.76 U2.41@681.1,1665.76 ; U1.6@635.86,2531.72 U1.41@740.19,2531.72 ; U1.4@635.86,2571.09 U1.41@720.5,2571.09 ; U1.2@635.86,2610.47 U1.41@681.13,2610.47 ; U2.40@661.42,1711.03 661.42,1685.44 U2.41@681.1,1665.76 ; U1.40@661.42,2655.74 661.45,2630.15 U1.41@681.13,2610.47 ; U2.39@681.1,1711.03 U2.41@681.1,1665.76 ; U1.39@681.1,2655.74 U1.41@681.13,2610.47 ; U2.13@700.79,1482.69 700.79,1547.65 U2.41@720.47,1567.33 ; U1.13@700.79,2427.39 700.82,2492.35 U1.41@720.5,2512.04 ; U2.14@720.47,1482.69 U2.41@720.47,1567.33 ; U1.14@720.47,2427.39 U1.41@720.5,2512.04 ; U2.34@779.53,1711.03 U2.41@779.53,1626.39 ; U1.34@779.56,2655.74 U1.41@779.56,2571.09 ; U2.31@838.58,1711.03 838.58,1685.44 U2.41@779.53,1626.39 ; U1.31@838.58,2655.74 838.61,2630.15 U1.41@779.56,2571.09 ; U3.18@846.97,1970.55 U3.17@846.97,1990.24 U3.16@846.97,2009.92 910.16,2009.92 v2(920,2019.77) 910.16,2029.61 U3.15@846.97,2029.61 U3.14@846.97,2049.3 U3.13@846.97,2068.98 ; U2.25@864.17,1587.02 759.84,1587.02 U2.41@750,1596.86 ; U1.25@864.17,2531.72 759.87,2531.72 U1.41@750,2541.57 ; U3.20@890.47,1955.06 U3.25@890.47,2000.33 ; U3.11@890.47,2092.8 U3.10@910.16,2092.8 ; U3.21@910.16,1955.06 U3.25@910.16,1990.49 ; U3.25@910.16,2039.7 U3.10@910.16,2092.8 ; 910.16,2104.66 U3.10@910.16,2092.8 ; U3.22@929.84,1955.06 U3.25@929.84,2020.02 ; U3.25@929.84,2039.7 929.84,2104.66 ; U3.23@949.53,1955.06 U3.25@949.53,2000.33 ; U3.25@949.53,2059.39 949.53,2104.66 ; U3.8@949.53,2092.8 U3.7@969.21,2092.8 ; v4(959,2525.36) 968.68,2535.04 968.68,2590.86 ; C28.1@963.68,1446 963.68,1477 980,1477 v1@1006,1451 ; U3.24@969.21,1946.74 U3.1@993.03,1970.55 U3.2@993.03,1990.24 ; U3.24@969.21,1955.06 U3.25@969.21,1975.68 ; 969.21,2079.07 U3.7@969.21,2092.8 ; 969.21,2104.66 U3.7@969.21,2092.8 ; U3.4@993.03,2029.61 U3.5@993.03,2049.3 U3.6@993.03,2068.98 U3.7@969.21,2092.8 ; U1.41@681.13,2610.47 U1.41@720.5,2571.09 ; U2.41@720.47,1567.33 U2.41@740.16,1587.02 ; U1.41@720.5,2512.04 U1.41@740.19,2531.72 ; U1.41@720.5,2571.09 U1.41@750,2541.57 ; U2.41@740.16,1587.02 U2.41@750,1596.86 ; U1.41@740.19,2531.72 U1.41@750,2541.57 ; U2.41@750,1596.86 U2.41@779.53,1626.39 ; U1.41@750,2541.57 U1.41@779.56,2571.09
  Top Layer w20: v1(536,2321) v1@536,2321.06 ; C20.2@567.28,1815.72 C20.2@569.21,1815.72 ; C31.1@834,1843.5 849.15,1843.5 ccw(c849.15,1885.7) v1(879,1855.86)
  Top Layer w25: C22.1@464.97,1678.83 C22.1@464.97,1680.64 ; C21.1@512.28,1709.72 C21.1@512.73,1709.72 ; C6.2@570.56,2756.47 C6.2@570.56,2757.44 ; C5.2@608.02,2795.84 C5.2@608.85,2795.84 ; D1.2@618.67,862 v1(647,862) ; v1(1200,740) D2.2@1200,775.33
  Top Layer w27: v1(536,1367) v1@536,1367.65
  Top Layer w30: v1(319,408.86) R6.1@355,410.36 ; R6.1@353.5,408.86 R6.1@355,410.36 ; R6.1@358,407.36 R6.1@355,410.36 ; v1(390,1452) R15.1@390,1483.5 ; R19.1@390,2556.5 v1(390,2588) ; v1(434,2293) R20.1@456.73,2315.73 ; v1(435,2647) 455.37,2626.63 C8.1@459.92,2626.63 ; v1(437.07,1348) R16.1@461.8,1372.73 ; v1(444,1657.86) C22.1@464.97,1678.83 ; v1(471,2093.13) R2_LF1.2@493.34,2115.47 ; v1(490,1732) C21.1@512.28,1709.72 ; v1(496,2667.47) C7.2@518.54,2644.94 ; v1@536,1367.65 C25.1@558.14,1389.8 ; v1@536,2321.06 C11.1@558.24,2343.29 ; v1(545,1838) C20.2@567.28,1815.72 ; v1(550,2778) C6.2@570.56,2757.44 ; v1(564,2274) C12.1@586.51,2296.51 ; R9.1@578,409.36 v1(614.27,409.36) uWire.6@614.27,291.01 ; v1(590,2813.86) C5.2@608.02,2795.84 ; v1(597,1244.48) C26.1@597,1275.5 ; v1(651,1256.86) 651,1289.91 C1_LF2.2@651.28,1290.19 ; C33.2@661,1889.87 v1(661,1921.86) ; v1(693,2218) C1_LF1.2@693,2251.36 ; R2_LF2.2@706,1201.5 706.5,1202 v1(738,1202) ; C32.1@716,1888.35 v1(716,1921) ; C18.2@722,2829.35 v1(722,2861.86) ; R11.1@770,410.36 v1(806,409) ; C4_LF2.2@770,1845.35 v1(770,1875.86) ; C4_LF1.2@780,2779.5 v1(780,2812) ; C17.2@852,2774.35 v1(852,2805.86) ; v1(879,1282) C27.2@879,1310.69 ; C16.2@912.05,2771.75 v1(912.05,2802.91)
  GND w10: v1(120.5,2965) 250,2965 v5(250,2862.4)
  GND w20: v3(1234.5,1514.65) cw(c1234.5,1499.15) 1250,1499.15 ; v3(1234.5,1976.92) cw(c1234.5,1961.42) 1250,1961.42 ; v3(1234.5,2459.36) 1234.5,2347.5 ccw(c1250,2347.5) 1250,2332 1250,2652 ; 1250,1388 1250,1499.15 ; 1250,1708 1250,1499.15 ; 1250,1850 1250,1961.42 ; 1250,2170 1250,1961.42
  Bottom Layer w10: R33.1@72.01,2488 R36.1@72.01,2543 ; R28.1@72.01,2829 R31.1@72.01,2884 R31.1@85,2884 ; J6.5@85,3025 v1(120.5,3025) ; U5.11@240.16,2438 240.16,2381.84 259.84,2362.16 C3.1@260,2362 ; U4.11@240.16,2780 240.16,2722.84 259.84,2703.16 C1.1@260,2703 ; U5.11@250,2484 v5(250,2521.4) 250,2523.37 U5.6@305.12,2523.37 ; U4.11@250,2825 v5(250,2862.4) 250,2864.37 U4.6@305.12,2864.37 ; R34.1@365,2551 R34.1@365,2546.99 cw(c369.84,2546.99) R34.1@369.84,2551.83 ; R29.1@365,2887.99 R29.1@365,2892.83 ; v2(721.26,2462.83) 752,2462.83 C36.1@752,2434.35 ; C37.2@863,2298.44 C37.2@864.44,2297 ; R23.2@913.98,2390 R23.2@917,2386.98 ; R25.2@974.3,1409.48 R25.2@976.78,1407
  Bottom Layer w15: v4(959,2525.36) 959,2538.32 C15.1@968.68,2548
  Bottom Layer w18: R31.1@82,2884 J6.5@82,3025
  Bottom Layer w20: U5.11@240.16,2530 240.16,2551.83 R34.1@365,2551.83 ; U4.11@240.16,2870 U4.11@240.16,2882.09 240.16,2892.84 259.84,2892.84 ; U4.11@259.84,2882 259.84,2892.84 ; R34.1@369.84,2551.83 C45.1@428,2551.83 ; C44.1@428,2892.83 365,2892.83 259.84,2892.84 ; C3_LF2.2@736.54,1872.36 C3_LF2.2@740.04,1875.86 ; C41.1@771,1510.38 v2(778.74,1518.12)
  Bottom Layer w25: C3_LF2.2@740.04,1875.86 v1(770,1875.86) ; C37.2@864.44,2297 v1(893,2297) ; v1(917,2363) R23.2@917,2384.98 ; R25.2@976.78,1407 v1(999,1407)
  Bottom Layer w30: R36.1@72.01,2543 v1(72,2575) ; U5.11@259.84,2530 U5.11@259.84,2545 ; U4.11@259.84,2870 U4.11@259.84,2882 ; C41.1@771,1487 C41.1@771,1510.38 ; C39.1@801.5,1688.88 C38.2@801.5,1720 ; C3_LF1.2@899.27,2769.27 899.27,2790.13 v1(912.05,2802.91)
  Bottom Layer w40: C3.1@259.84,2362.16 U5.11@259.84,2426.91 U5.11@259.84,2438 ; C1.1@259.84,2703.16 U4.11@259.84,2780
  Bottom Layer w45: C3.1@260,2362 C4.1@341.54,2362 ; C1.1@260,2703 C2.1@356.07,2703
  other v1: 50,1347.5 110,1347.5 170,1347.5 1010,1451 941,1631.86 1009,1632 1009,1682 941,1682.86 50,1692.5 110,1692.5 170,1692.5 941,1731.86 1009,1732 940,1779.86 1009,1782 911,1823.86 994,1834.86 50,1847.5 110,1847.5 170,1847.5 958,1868.86 928,1899 925,2134.86 843,2150.86 964,2170.86 878,2186.86 50,2192.5 110,2192.5 170,2192.5 999,2203.86 910,2220.86 938,2255 1009,2255 939,2304.86 1009,2305 1009,2355 1009,2405 465.5,2965 465.5,3025 120.5,3085 465.5,3085
  other v2: 721.26,1518.12 671.26,1568.12 721.26,1568.12 778.74,1568.12 828.74,1568.12 671.26,1625.6 721.26,1625.6 778.74,1625.6 828.74,1625.6 721.26,1675.6 778.74,1675.6 920,1980.4 880.63,2019.77 959.37,2019.77 920,2059.14 778.74,2462.83 671.26,2512.83 721.26,2512.83 778.74,2512.83 828.74,2512.83 671.26,2570.31 721.26,2570.31 778.74,2570.31 828.74,2570.31 721.26,2620.31 778.74,2620.31
  other v3: 1060.5,1514.65 1147.5,1514.65 1060.5,1580.65 1147.5,1580.65 1234.5,1580.65 1060.5,1976.92 1147.5,1976.92 1060.5,2042.92 1147.5,2042.92 1234.5,2042.92 1060.5,2459.36 1147.5,2459.36 1060.5,2525.36 1147.5,2525.36 1234.5,2525.36
  other v4: 954,1519 939,1581.86 942,2452
  other v5: 250,2446.6 227.36,2484 272.64,2484 250,2787.6 227.36,2825 272.64,2825
NetC1_LF1_1: C1_LF1.1 C2_LF1.1 R3_LF1.1 U1.12 | length 690.2
  Top Layer w10: C2_LF1.1@622.22,2244.08 C2_LF1.1@622.22,2248.58 ; U1.12@681.1,2427.39 681.1,2381.48 ccw(c711.48,2381.48) 690,2360 698.05,2351.95 cw(c686.1,2340) 703,2340 703,2324.35 693.65,2315 C1_LF1.1@693,2314.35
  Top Layer w15: C2_LF1.1@622.22,2248.58 C1_LF1.1@677.25,2303.61
  Top Layer w25: C1_LF1.1@693.65,2315 v1(724,2315)
  Bottom Layer w10: R3_LF1.1@695.04,2711.53 641,2657.48 641,2433.86 685,2389.86 685,2354 v1(724,2315)
NetC1_LF2_1: C1_LF2.1 C2_LF2.1 R3_LF2.1 U2.12 | length 554.9
  Top Layer w10: C1_LF2.1@651.28,1353.18 C1_LF2.1@651.28,1360.14 ; U2.12@681.1,1482.69 681.1,1452.76 700,1433.86 ; C2_LF2.1@700.72,1380.86 C2_LF2.1@706.21,1386.35
  Top Layer w15: C2_LF2.1@700,1392.57 700,1433.86
  Top Layer w20: C1_LF2.1@651.28,1360.14 v1(672,1380.86) C2_LF2.1@700.72,1380.86
  Bottom Layer w10: R3_LF2.1@661.09,1729.95 R3_LF2.1@661.09,1735.48 ; v1(672,1380.86) 641,1411.86 641,1715.39 R3_LF2.1@661.09,1735.48 ; R3_LF2.1@661.09,1735.48 R3_LF2.1@661.09,1736.95 R3_LF2.1@661.09,1735.48
NetC2_LF1_2: C2_LF1.2 R2_LF1.1 | length 56.2
  Top Layer w20: R2_LF1.1@538.15,2160.01 C2_LF1.2@577.68,2199.54
  Top Layer w30: R2_LF1.1@537.88,2160.01 R2_LF1.1@538.15,2160.01
NetC2_LF2_2: C2_LF2.2 R2_LF2.1 | length 54.6
  Top Layer w20: C2_LF2.2@706.21,1323.36 707,1322.58 R2_LF2.1@707,1269.08
NetC3_LF1_1: C3_LF1.1 R3_LF1.2 R4_LF1.1 | length 199.1
  Bottom Layer w10: R3_LF1.2@739.59,2756.07 823.39,2756.07 854.73,2724.73 854.73,2692.84 R4_LF1.1@827.71,2665.82
  Bottom Layer w30: R4_LF1.1@827.71,2665.82 R4_LF1.1@828.34,2665.19
NetC3_LF2_1: C3_LF2.1 R3_LF2.2 R4_LF2.1 | length 156.3
  Bottom Layer w20: C3_LF2.1@673.55,1872.36 682,1863.9 682,1839.95 R4_LF2.1@707.68,1814.27 724.08,1797.87 R3_LF2.2@724.08,1736.95
NetC4_LF1_1: C4_LF1.1 R4_LF1.2 U1.35 | length 182.9
  Top Layer w10: U1.35@759.84,2655.74 759.84,2695.02 C4_LF1.1@780.66,2715.84 ; C4_LF1.1@780,2716.5 C4_LF1.1@780.66,2715.84 ; C4_LF1.1@780.83,2716 C4_LF1.1@780.66,2715.84 ; C4_LF1.1@782.5,2714 C4_LF1.1@780.66,2715.84
  Top Layer w20: C4_LF1.1@780.83,2716 v4(807,2716)
  Bottom Layer w20: R4_LF1.2@764.72,2665.82 764.72,2696.72 cw(c784,2696.72) 784,2716 v4(807,2716)
NetC4_LF2_1: C4_LF2.1 R4_LF2.2 U2.35 | length 127.6
  Top Layer w10: U2.35@759.84,1711.03 C4_LF2.1@759.84,1766.86 ; C4_LF2.1@770,1782.36 C4_LF2.1@772.36,1780
  Top Layer w15: C4_LF2.1@772.36,1780 v4(796,1780)
  Bottom Layer w20: R4_LF2.2@770.67,1814.27 796,1788.94 v4(796,1780)
NetC6_1: C6.1 U1.38 | length 136.7
  Top Layer w10: C6.1@633.93,2711.93 C6.1@615.1,2711.93 634.17,2692.86 678.88,2692.86 700.82,2670.92 U1.38@700.79,2655.74
NetC7_1: C7.1 U1.3 | length 76.7
  Top Layer w10: C7.1@563.08,2600.4 581.61,2600.4 591.22,2590.78 U1.3@635.83,2590.78
NetC9_2: C9.2 U1.8 | length 127.3
  Top Layer w10: C9.2@508.5,2492.35 U1.8@635.83,2492.35
NetC10_1: C10.1 R20.2 | length 53.6
  Top Layer w30: R20.2@500.61,2361.61 C10.1@538.51,2399.51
